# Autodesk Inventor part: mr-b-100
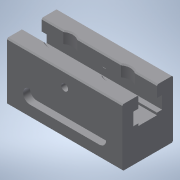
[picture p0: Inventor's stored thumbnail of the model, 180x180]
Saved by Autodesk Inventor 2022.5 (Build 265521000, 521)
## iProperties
Created: 2016-12
Part Number: mr-b-100
Material: 一般
Document SubType Name: Modeling
Designer: imaocorp
Density: 1 g/cm^3
Appearance: 既定
Author: imaocorp
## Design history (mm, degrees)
node "mr-b-100.x_t1"
node "mr-b-100"
node "Base1"
